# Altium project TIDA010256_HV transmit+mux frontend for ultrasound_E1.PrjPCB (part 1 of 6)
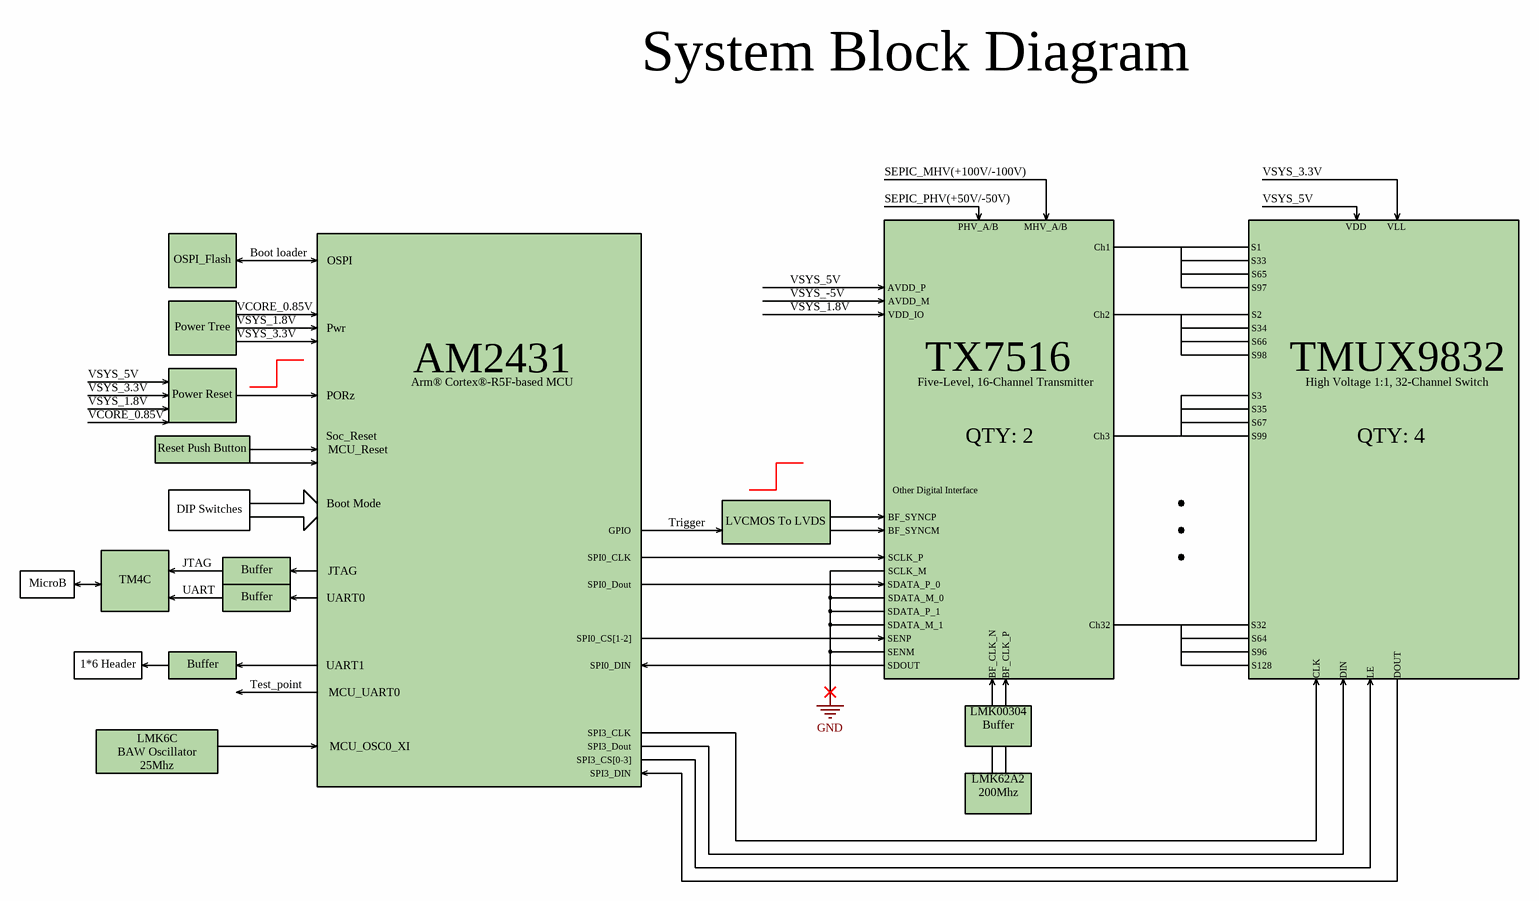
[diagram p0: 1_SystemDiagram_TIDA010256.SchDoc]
CopyrightYear: 2023; PCB_Layout: Jason Ding / Michael Rosa; PCB_Rev: E1; PRJ_Customer: Public Release; PRJ_Engineer: Sanjay Pithadia; PRJ_Number: TIDA-010256; PRJ_Title: HV transmit+mux frontend for ultrasound; SCH_Rev: E1; TechSupport: http://www.ti.com/support; TID: TIDA-010256
18 sheets, 806 parts. Net scope: global (net labels, ports and power ports of the same name join across sheets).
Board file: TIDA010256_HV transmit+mux frontend for ultrasound_E1.PcbDoc
Sheets:
  1_SystemDiagram_TIDA010256.SchDoc
  10_Power_Tree.SchDoc
  11_HighVoltage_PowerSupply.SchDoc
  12_LowVoltage_PowerSupplies01.SchDoc
  13_LowVoltage_PowerSupplies02.SchDoc
  14_XDS110_Debugger.SchDoc
  15_AM243x_BootMode.SchDoc
  16_AM243x_Reset.SchDoc
  17_AM243x_SocPower.SchDoc
  18_AM243x_Pinout.SchDoc
  19_Clock_Gen.SchDoc
  20_TX7516_PartAPinout.SchDoc
  21_TX7516_PartBPinout.SchDoc
  22_TMUX9832(0-64)_Pinout.SchDoc
  23_TMUX9832(65-128)_Pinout.SchDoc
  24_TX_Connector(no load resitor).SchDoc
  25_RX_Connector.SchDoc
  Hardware.SchDoc

## Sheet 1_SystemDiagram_TIDA010256.SchDoc
size 431 x 279 mm; Date: Not shown in title block; ApprovedBy: Not shown in title block; CheckedBy: Not shown in title block; Author: Not shown in title block; CompanyName: Not shown in title block; DrawnBy: Jason Ding; Engineer: Not shown in title block; Organization: Not shown in title block; Address1: Not shown in title block; Address2: Not shown in title block; Address3: Not shown in title block; Address4: Not shown in title block; DocumentNumber: 1; Revision: Use project parameter SCH_Rev; SheetNumber: 1; SheetTotal: 18; PageSetup: Record=PageOptions¦CenterHorizontal=True¦CenterVertical=True¦PrintScale=1.00¦XCorrection=1.00¦YCorrection=1.00¦PrintKind=0¦BorderSize=5000000¦LeftOffset=0¦BottomOffset=0¦Orientation=2¦PaperLength=1000¦PaperWidth=1000¦Scale=100¦PaperSource=15¦PrintQuality=600¦MediaType=1¦DitherType=10¦PaperKind=Letter¦PrintScaleMode=1

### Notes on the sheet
- System Block Diagram
- SEPIC_MHV(+100V/-100V)
- VSYS_3.3V
- OSPI_Flash
- Boot loader
- OSPI
- SEPIC_PHV(+50V/-50V)
- PHV_A/B
- MHV_A/B
- Ch1
- S1
- S33
- VSYS_5V
- VDD
- VLL
- VCORE_0.85V
- VSYS_1.8V
- Pwr
- VSYS_-5V
- VDD_IO
- AVDD_P
- AVDD_M
- Ch2
- S2
- S34
- S65
- S97
- Power Reset
- Power Tree
- PORz
- AM2431
- Arm® Cortex®-R5F-based MCU
- TX7516
- Five-Level, 16-Channel Transmitter
- S3
- S98
- S66
- TMUX9832
- High Voltage 1:1, 32-Channel Switch
- Reset Push Button
- Soc_Reset
- MCU_Reset
- QTY: 2
- Ch3
- S35
- S99
- S67
- QTY: 4
- DIP Switches
- Boot Mode
- GPIO
- Trigger
- LVCMOS To LVDS
- BF_SYNCP
- BF_SYNCM
- Other Digital Interface
- MicroB
- TM4C
- JTAG
- UART
- Buffer
- UART0
- SPI0_CLK
- SPI0_Dout
- SCLK_P
- SCLK_M
- SDATA_P_0
- SDATA_M_0
- 1*6 Header
- UART1
- SPI0_CS[1-2]
- SPI0_DIN
- SENP
- SENM
- SDOUT
- SDATA_P_1
- SDATA_M_1
- Ch32
- S32
- S64
- S96
- S128
- Test_point
- MCU_UART0
- SPI3_CLK
- LMK00304
- BF_CLK_N
- BF_CLK_P
- CLK
- DIN
- LE
- DOUT
- BAW Oscillator
- LMK6C
- 25Mhz
- MCU_OSC0_XI
- SPI3_CS[0-3]
- SPI3_Dout
- SPI3_DIN
- LMK62A2
- 200Mhz
- Labels drawn without touching a wire or pin: GND

## Sheet 10_Power_Tree.SchDoc
size 431 x 279 mm; Date: Not shown in title block; ApprovedBy: Not shown in title block; CheckedBy: Not shown in title block; Author: Not shown in title block; CompanyName: Not shown in title block; Engineer: Not shown in title block; Organization: Not shown in title block; Address1: Not shown in title block; Address2: Not shown in title block; Address3: Not shown in title block; Address4: Not shown in title block; DocumentNumber: 2; Revision: Use project parameter SCH_Rev; SheetNumber: 2; SheetTotal: 18; PageSetup: Record=PageOptions¦CenterHorizontal=True¦CenterVertical=True¦PrintScale=1.00¦XCorrection=1.00¦YCorrection=1.00¦PrintKind=0¦BorderSize=5000000¦LeftOffset=0¦BottomOffset=0¦Orientation=2¦PaperLength=1000¦PaperWidth=1000¦Scale=100¦PaperSource=15¦PrintQuality=600¦MediaType=1¦DitherType=10¦PaperKind=Letter¦PrintScaleMode=1
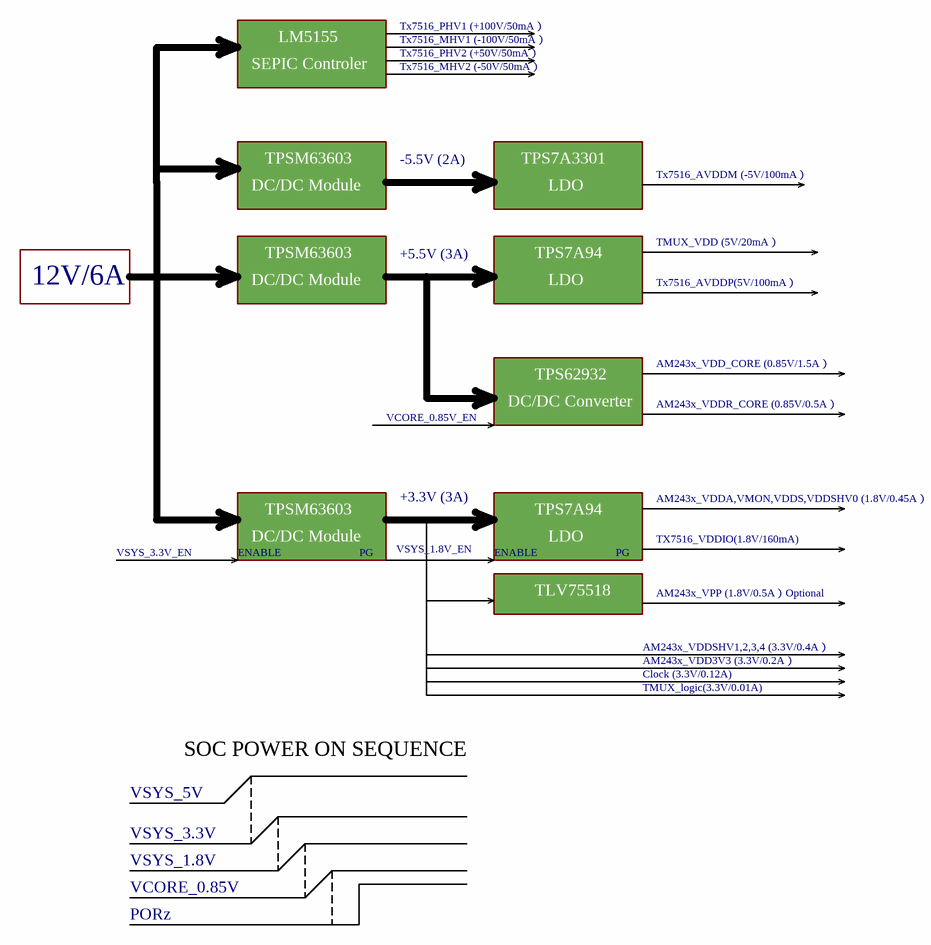
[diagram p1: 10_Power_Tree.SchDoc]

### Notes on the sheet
- LM5155
- Tx7516_PHV1 (+100V/50mA）
- Tx7516_MHV1 (-100V/50mA）
- Tx7516_PHV2 (+50V/50mA）
- SEPIC Controler
- Tx7516_MHV2 (-50V/50mA）
- DC/DC Module
- TPSM63603
- -5.5V (2A)
- TPS7A3301
- LDO
- Tx7516_AVDDM (-5V/100mA）
- +5.5V (3A)
- TPS7A94
- TMUX_VDD (5V/20mA）
- 12V/6A
- Tx7516_AVDDP(5V/100mA）
- TPS62932
- AM243x_VDD_CORE (0.85V/1.5A）
- VCORE_0.85V_EN
- DC/DC Converter
- AM243x_VDDR_CORE (0.85V/0.5A）
- +3.3V (3A)
- AM243x_VDDA,VMON,VDDS,VDDSHV0 (1.8V/0.45A）
- VSYS_3.3V_EN
- ENABLE
- PG
- VSYS_1.8V_EN
- TLV75518
- TX7516_VDDIO(1.8V/160mA)
- AM243x_VPP (1.8V/0.5A）Optional
- AM243x_VDDSHV1,2,3,4 (3.3V/0.4A）
- AM243x_VDD3V3 (3.3V/0.2A）
- Clock (3.3V/0.12A)
- TMUX_logic(3.3V/0.01A)
- VSYS_5V
- SOC POWER ON SEQUENCE
- VSYS_3.3V
- VSYS_1.8V
- VCORE_0.85V
- PORz

## Sheet 11_HighVoltage_PowerSupply.SchDoc
size A2; Date: Not shown in title block; ApprovedBy: Not shown in title block; CheckedBy: Not shown in title block; Author: Not shown in title block; CompanyName: Not shown in title block; Engineer: Not shown in title block; Organization: Not shown in title block; Address1: Not shown in title block; Address2: Not shown in title block; Address3: Not shown in title block; Address4: Not shown in title block; DocumentNumber: 3; Revision: Use project parameter SCH_Rev; SheetNumber: 3; SheetTotal: 18; PageSetup: Record=PageOptions¦CenterHorizontal=True¦CenterVertical=True¦PrintScale=0.69¦XCorrection=1.00¦YCorrection=1.00¦PrintKind=0¦BorderSize=5000000¦LeftOffset=0¦BottomOffset=0¦Orientation=2¦PaperLength=1000¦PaperWidth=1000¦Scale=100¦PaperSource=15¦PrintQuality=600¦MediaType=1¦DitherType=10¦PaperKind=Letter¦PrintScaleMode=1
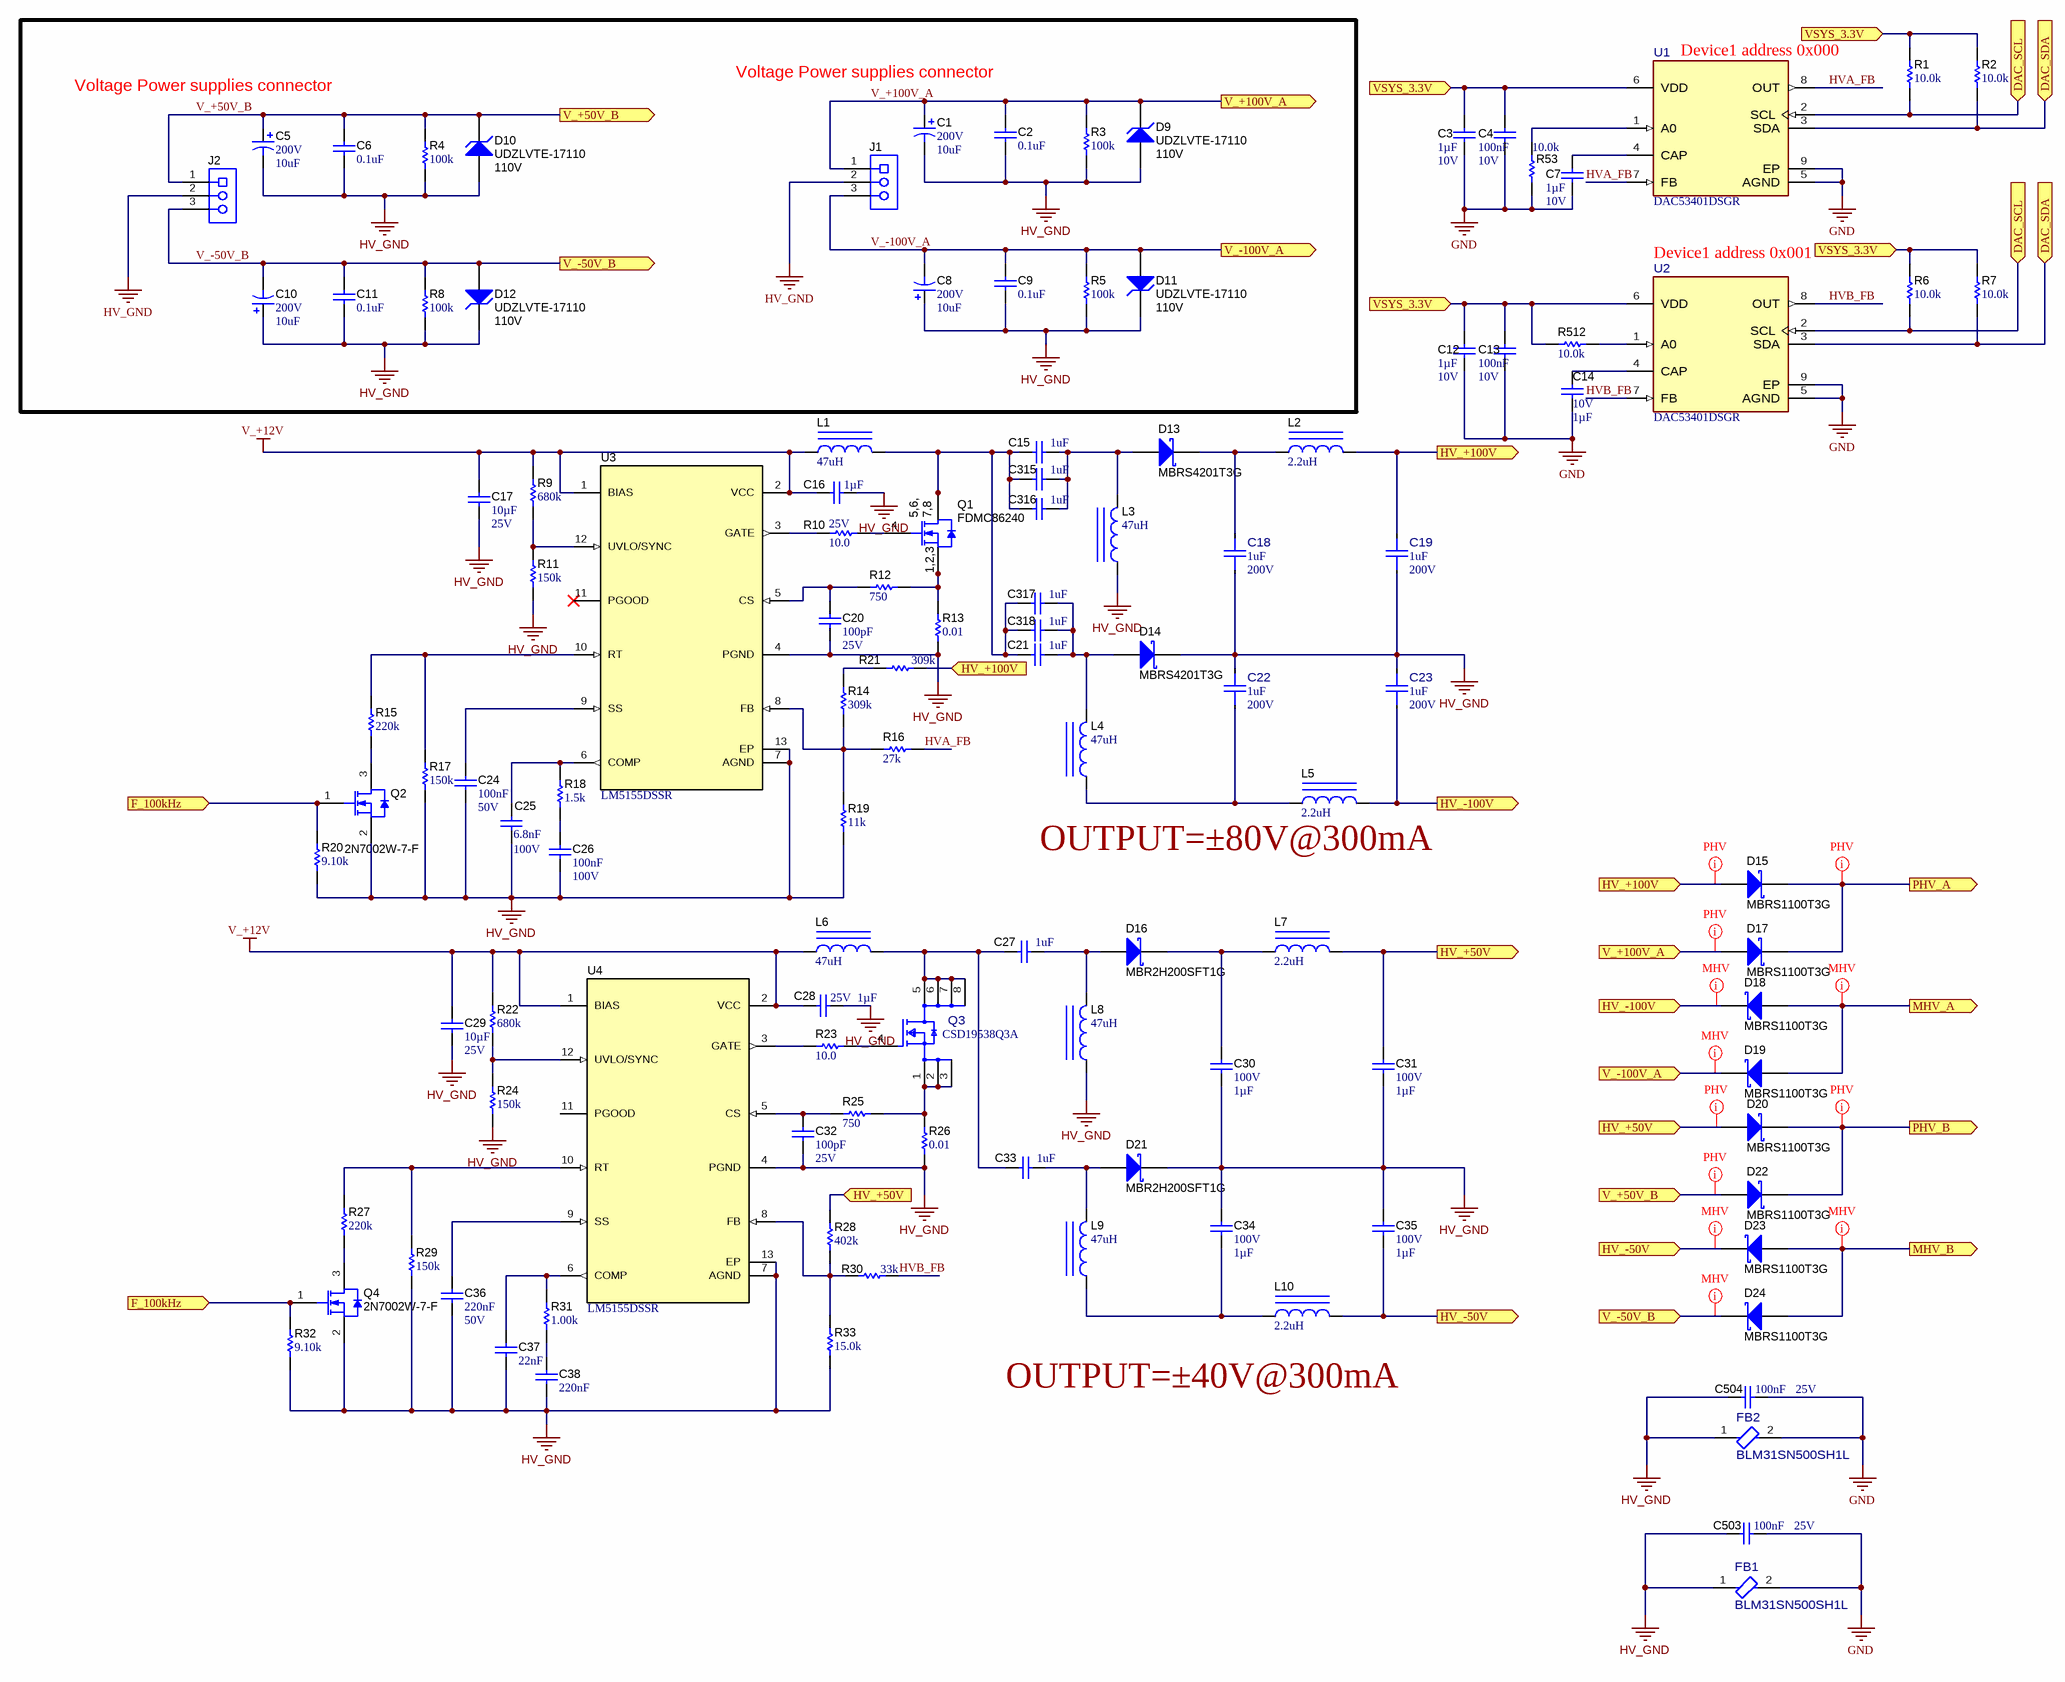
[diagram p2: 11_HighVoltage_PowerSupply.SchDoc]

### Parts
C1  VDC_V: 200V  ValueDisplayed: 10uF  [CAPPRD350W60D800H1150]  (hidden comment: 200LLE10MEFC8X11.5)
C2  ValueDisplayed: 0.1uF  [1206]  (hidden comment: C1206C104K2RACTU)
C3  Cap_F: 1µF  VDC_V: 10V  [0603]  (hidden comment: C0603X105J8RAC7867)
C4  Cap_F: 100nF  VDC_V: 10V  [0603]  (hidden comment: C0603C104K8RACTU)
C5  VDC_V: 200V  ValueDisplayed: 10uF  [CAPPRD350W60D800H1150]  (hidden comment: 200LLE10MEFC8X11.5)
C6  ValueDisplayed: 0.1uF  [1206]  (hidden comment: C1206C104K2RACTU)
C7  Cap_F: 1µF  VDC_V: 10V  [0603]  (hidden comment: C0603X105J8RAC7867)
C8  VDC_V: 200V  ValueDisplayed: 10uF  [CAPPRD350W60D800H1150]  (hidden comment: 200LLE10MEFC8X11.5)
C9  ValueDisplayed: 0.1uF  [1206]  (hidden comment: C1206C104K2RACTU)
C10  VDC_V: 200V  ValueDisplayed: 10uF  [CAPPRD350W60D800H1150]  (hidden comment: 200LLE10MEFC8X11.5)
C11  ValueDisplayed: 0.1uF  [1206]  (hidden comment: C1206C104K2RACTU)
C12  Cap_F: 1µF  VDC_V: 10V  [0603]  (hidden comment: C0603X105J8RAC7867)
C13  Cap_F: 100nF  VDC_V: 10V  [0603]  (hidden comment: C0603C104K8RACTU)
C14  Cap_F: 1µF  VDC_V: 10V  [0603]  (hidden comment: C0603X105J8RAC7867)
C15  ValueDisplayed: 1uF  [1206_180]  (hidden comment: GRM31CR72A105KA01L)
C16  Cap_F: 1µF  VDC_V: 25V  [0603]  (hidden comment: 06033C105KAT2A)
C17  Cap_F: 10µF  VDC_V: 25V  [0805_HV]  (hidden comment: GRM21BZ71E106KE15L)
C18  ValueDisplayed: 1uF  VDC_V: 200V  [FP-1812Y2500105KXTWS2_1812-MFG]  (hidden comment: 18122C105JAT2A)
C19  ValueDisplayed: 1uF  VDC_V: 200V  [FP-1812Y2500105KXTWS2_1812-MFG]  (hidden comment: 18122C105JAT2A)
C20  Cap_F: 100pF  VDC_V: 25V  [0603]  (hidden comment: 06033C101KAT2A)
C21  ValueDisplayed: 1uF  [1206_180]  (hidden comment: GRM31CR72A105KA01L)
C22  ValueDisplayed: 1uF  VDC_V: 200V  [FP-1812Y2500105KXTWS2_1812-MFG]  (hidden comment: 18122C105JAT2A)
C23  ValueDisplayed: 1uF  VDC_V: 200V  [FP-1812Y2500105KXTWS2_1812-MFG]  (hidden comment: 18122C105JAT2A)
C24  Cap_F: 100nF  VDC_V: 50V  [0603]  (hidden comment: GRM188R71H224KAC4D)
C25  Cap_F: 6.8nF  VDC_V: 100V  [0603]  (hidden comment: GRM188R72A682KA01D)
C26  Cap_F: 100nF  VDC_V: 100V  [0603]  (hidden comment: GRM188R72A104KA35D)
C27  ValueDisplayed: 1uF  [1206_180]  (hidden comment: GRM31CR72A105KA01L)
C28  Cap_F: 1µF  VDC_V: 25V  [0603]  (hidden comment: 06033C105KAT2A)
C29  Cap_F: 10µF  VDC_V: 25V  [0805_HV]  (hidden comment: GRM21BZ71E106KE15L)
C30  VDC_V: 100V  ValueDisplayed: 1µF  [0805_HV]  (hidden comment: C2012X7S2A105K125AE)
C31  VDC_V: 100V  ValueDisplayed: 1µF  [0805_HV]  (hidden comment: C2012X7S2A105K125AE)
C32  Cap_F: 100pF  VDC_V: 25V  [0603]  (hidden comment: 06033C101KAT2A)
C33  ValueDisplayed: 1uF  [1206_180]  (hidden comment: GRM31CR72A105KA01L)
C34  VDC_V: 100V  ValueDisplayed: 1µF  [0805_HV]  (hidden comment: C2012X7S2A105K125AE)
C35  VDC_V: 100V  ValueDisplayed: 1µF  [0805_HV]  (hidden comment: C2012X7S2A105K125AE)
C36  Cap_F: 220nF  VDC_V: 50V  [0603]  (hidden comment: GRM188R71H224KAC4D)
C37  Cap_F: 22nF  [0603]  (hidden comment: 885012206034)
C38  Cap_F: 220nF  [0603]  (hidden comment: 885012206048)
C315  ValueDisplayed: 1uF  [1206_180]  (hidden comment: GRM31CR72A105KA01L)
C316  ValueDisplayed: 1uF  [1206_180]  (hidden comment: GRM31CR72A105KA01L)
C317  ValueDisplayed: 1uF  [1206_180]  (hidden comment: GRM31CR72A105KA01L)
C318  ValueDisplayed: 1uF  [1206_180]  (hidden comment: GRM31CR72A105KA01L)
C503  Cap_F: 100nF  VDC_V: 25V  [0603]  (hidden comment: C0603C104J3RAC)
C504  Cap_F: 100nF  VDC_V: 25V  [0603]  (hidden comment: C0603C104J3RAC)
D9  UDZLVTE-17110  value 110V  [SOD-323F]
D10  UDZLVTE-17110  value 110V  [SOD-323F]
D11  UDZLVTE-17110  value 110V  [SOD-323F]
D12  UDZLVTE-17110  value 110V  [SOD-323F]
D13  MBRS4201T3G  [SMC]
D14  MBRS4201T3G  [SMC]
D15  MBRS1100T3G  [SMB]
D16  MBR2H200SFT1G  [SOD-123FL]
D17  MBRS1100T3G  [SMB]
D18  MBRS1100T3G  [SMB]
D19  MBRS1100T3G  [SMB]
D20  MBRS1100T3G  [SMB]
D21  MBR2H200SFT1G  [SOD-123FL]
D22  MBRS1100T3G  [SMB]
D23  MBRS1100T3G  [SMB]
D24  MBRS1100T3G  [SMB]
FB1  BLM31SN500SH1L  [FP-BLM31SN500SH1L_1206-MFG]
FB2  BLM31SN500SH1L  [FP-BLM31SN500SH1L_1206-MFG]
J1  1725669  [Phoenix_1725669]  (value not drawn)
J2  1725669  [Phoenix_1725669]  (value not drawn)
L1  ValueDisplayed: 47uH  [WE-PD_1210]  (hidden comment: 7447709470)
L2  ValueDisplayed: 2.2uH  [0603]  (hidden comment: LQM18PN2R2MFR)
L3  ValueDisplayed: 47uH  [WE-PD2-XL]  (hidden comment: 744776147)
L4  ValueDisplayed: 47uH  [WE-PD2-XL]  (hidden comment: 744776147)
L5  ValueDisplayed: 2.2uH  [0603]  (hidden comment: LQM18PN2R2MFR)
L6  ValueDisplayed: 47uH  [WE-PD_1210]  (hidden comment: 7447709470)
L7  ValueDisplayed: 2.2uH  [0603]  (hidden comment: LQM18PN2R2MFR)
L8  ValueDisplayed: 47uH  [WE-PD2-XL]  (hidden comment: 744776147)
L9  ValueDisplayed: 47uH  [WE-PD2-XL]  (hidden comment: 744776147)
L10  ValueDisplayed: 2.2uH  [0603]  (hidden comment: LQM18PN2R2MFR)
Q1  FDMC86240  [TRANS_Fairchild_MLP08S]
Q2  2N7002W-7-F  [SOT-323]
Q3  CSD19538Q3A  [DNH0008A-MFG]
Q4  2N7002W-7-F  [SOT-323]
R1  ValueDisplayed: 10.0k  [0603]  (hidden comment: RNCF0603TKY10K0)
R2  ValueDisplayed: 10.0k  [0603]  (hidden comment: RNCF0603TKY10K0)
R3  ValueDisplayed: 100k  [1206]  (hidden comment: TNPW1206100KBEEA)
R4  ValueDisplayed: 100k  [1206]  (hidden comment: TNPW1206100KBEEA)
R5  ValueDisplayed: 100k  [1206]  (hidden comment: TNPW1206100KBEEA)
R6  ValueDisplayed: 10.0k  [0603]  (hidden comment: RNCF0603TKY10K0)
R7  ValueDisplayed: 10.0k  [0603]  (hidden comment: RNCF0603TKY10K0)
R8  ValueDisplayed: 100k  [1206]  (hidden comment: TNPW1206100KBEEA)
R9  ValueDisplayed: 680k  [0805_HV]  (hidden comment: CRCW0805215KFKEA)
R10  ValueDisplayed: 10.0  [0603]  (hidden comment: CRCW060310R0FKEA)
R11  ValueDisplayed: 150k  [0805_HV]  (hidden comment: CRCW0805215KFKEA)
R12  ValueDisplayed: 750  [0603]  (hidden comment: CRCW0603750RFKEA)
R13  ValueDisplayed: 0.01  [0612]  (hidden comment: ERJ-B2CFR01V)
R14  ValueDisplayed: 309k  [0603]  (hidden comment: CRCW0603309KFKEA)
R15  ValueDisplayed: 220k  [0603]  (hidden comment: RG1608P-224-B-T5)
R16  ValueDisplayed: 27k  [0603]  (hidden comment: CRCW060327K0JNEA)
R17  ValueDisplayed: 150k  [0603]  (hidden comment: RT0603BRD07150KL)
R18  ValueDisplayed: 1.5k  [0603]  (hidden comment: CRCW06031K50JNEA)
R19  ValueDisplayed: 11k  [0603]  (hidden comment: CRCW060311K0JNEA)
R20  ValueDisplayed: 9.10k  [0603]  (hidden comment: RG1608P-912-B-T5)
R21  ValueDisplayed: 309k  [0603]  (hidden comment: CRCW0603309KFKEA)
R22  ValueDisplayed: 680k  [0805_HV]  (hidden comment: CRCW0805215KFKEA)
R23  ValueDisplayed: 10.0  [0603]  (hidden comment: CRCW060310R0FKEA)
R24  ValueDisplayed: 150k  [0805_HV]  (hidden comment: CRCW0805215KFKEA)
R25  ValueDisplayed: 750  [0603]  (hidden comment: CRCW0603750RFKEA)
R26  ValueDisplayed: 0.01  [0612]  (hidden comment: ERJ-B2CFR01V)
R27  ValueDisplayed: 220k  [0603]  (hidden comment: RG1608P-224-B-T5)
R28  ValueDisplayed: 402k  [0603]  (hidden comment: CRCW0603402KFKEA)
R29  ValueDisplayed: 150k  [0603]  (hidden comment: RT0603BRD07150KL)
R30  ValueDisplayed: 33k  [0603]  (hidden comment: CRCW060333K0JNEA)
R31  ValueDisplayed: 1.00k  [0603]  (hidden comment: RC0603FR-071KL)
R32  ValueDisplayed: 9.10k  [0603]  (hidden comment: RG1608P-912-B-T5)
R33  ValueDisplayed: 15.0k  [0603]  (hidden comment: CRCW060315K0FKEA)
R53  ValueDisplayed: 10.0k  [0603]  (hidden comment: RNCF0603TKY10K0)
R512  ValueDisplayed: 10.0k  [0603]  (hidden comment: RNCF0603TKY10K0)
U1  DAC53401DSGR  [DSG0008A-MFG]
U2  DAC53401DSGR  [DSG0008A-MFG]
U3  LM5155DSSR  [DSS0012B]
U4  LM5155DSSR  [DSS0012B]

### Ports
DAC_SCL (in), DAC_SDA (in), F_100kHz (in), HV_+50V (in), HV_+50V (out), HV_+100V (in), HV_+100V (out), HV_-50V (in), HV_-50V (out), HV_-100V (in), HV_-100V (out), MHV_A (out), MHV_B (out), PHV_A (out), PHV_B (out), V_+50V_B (in), V_+50V_B (out), V_+100V_A (in), V_+100V_A (out), V_-50V_B (in), V_-50V_B (out), V_-100V_A (in), V_-100V_A (out), VSYS_3.3V (in)

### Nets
GND: C3.2 C4.2 C7.2 C12.2 C13.2 C14.2 C503.1 C504.1 FB1.2 FB2.2 R53.1 U1.5(AGND) U1.9(EP) U2.5(AGND) U2.9(EP)
HV_GND: C1.2(-) C2.2 C5.2(-) C6.2 C8.1(+) C9.2 C10.1(+) C11.2 C16.2 C17.2 C18.1 C19.1 C20.2 C22.2 C23.2 C24.2 C25.2 C26.2 C28.2 C29.2 C30.2 C31.2 C32.2 C34.1 C35.1 C36.2 C37.2 C38.2 C503.2 C504.2 D9.2(A) D10.2(A) D11.1(K) D12.1(K) D14.1(K) D21.1(K) FB1.1 FB2.1 J1.2 J2.2 L3.1 L8.1 Q2.2(S) Q4.2(S) R3.1 R4.1 R5.1 R8.1 R11.1 R13.1 R17.1 R19.1 R20.1 R24.1 R26.1 R29.1 R32.1 R33.1 U3.4(PGND) U3.7(AGND) U3.13(EP) U4.4(PGND) U4.7(AGND) U4.13(EP)
MHV_A: D18.2(A) D19.2(A) ; port MHV_A
MHV_B: D23.2(A) D24.2(A) ; port MHV_B
PHV_A: D15.1(K) D17.1(K) ; port PHV_A
PHV_B: D20.1(K) D22.1(K) ; port PHV_B
V_+12V: C16.1 C17.1 C28.1 C29.1 L1.1 L6.1 R9.2 R22.2 U3.1(BIAS) U3.2(VCC) U4.1(BIAS) U4.2(VCC)
HVA_FB: R16.2 U1.7(FB) U1.8(OUT)
HVB_FB: R30.2 U2.7(FB) U2.8(OUT)
V_+50V_B: C5.1(+) C6.1 D10.1(K) D22.2(A) J2.1 R4.2 ; port V_+50V_B
V_+100V_A: C1.1(+) C2.1 D9.1(K) D17.2(A) J1.1 R3.2 ; port V_+100V_A
V_-50V_B: C10.2(-) C11.1 D12.2(A) D24.1(K) J2.3 R8.2 ; port V_-50V_B
V_-100V_A: C8.2(-) C9.1 D11.2(A) D19.1(K) J1.3 R5.2 ; port V_-100V_A
VSYS_3.3V: C3.1 C4.1 C12.1 C13.1 R1.2 R2.2 R6.2 R7.2 R512.2 U1.6(VDD) U2.6(VDD) ; port VSYS_3.3V
NetC7_1: C7.1 U1.4(CAP)
NetC14_1: C14.1 U2.4(CAP)
NetC15_1: C15.1 C315.1 C316.1 D13.2(A) L3.2
NetC15_2: C15.2 C21.2 C315.2 C316.2 C317.2 C318.2 L1.2 Q1.5(D) Q1.6(D) Q1.7(D) Q1.8(D) Q1.9(D)
NetC18_2: C18.2 D13.1(K) L2.1
NetC19_2: C19.2 D15.2(A) L2.2 R21.1 ; port HV_+100V
NetC20_1: C20.1 R12.1 U3.5(CS)
NetC21_1: C21.1 C317.1 C318.1 D14.2(A) L4.2
NetC22_1: C22.1 L4.1 L5.1
NetC23_1: C23.1 D18.1(K) L5.2 ; port HV_-100V
NetC24_1: C24.1 U3.9(SS)
NetC25_1: C25.1 R18.2 U3.6(COMP)
NetC26_1: C26.1 R18.1
NetC27_1: C27.1 D16.2(A) L8.2
NetC27_2: C27.2 C33.2 L6.2 Q3.5(D) Q3.6(D) Q3.7(D) Q3.8(D)
NetC30_1: C30.1 D16.1(K) L7.1
NetC31_1: C31.1 D20.2(A) L7.2 R28.2 ; port HV_+50V
NetC32_1: C32.1 R25.1 U4.5(CS)
NetC33_1: C33.1 D21.2(A) L9.2
NetC34_2: C34.2 L9.1 L10.1
NetC35_2: C35.2 D23.1(K) L10.2 ; port HV_-50V
NetC36_1: C36.1 U4.9(SS)
NetC37_1: C37.1 R31.2 U4.6(COMP)
NetC38_1: C38.1 R31.1
NetQ1_1: Q1.1(S) Q1.2(S) Q1.3(S) R12.2 R13.2
NetQ1_4: Q1.4(G) R10.2
NetQ2_1: Q2.1(G) Q4.1(G) R20.2 R32.2 ; port F_100kHz
NetQ2_3: Q2.3(D) R15.1
NetQ3_1: Q3.1(S) Q3.2(S) Q3.3(S) R25.2 R26.2
NetQ3_4: Q3.4(G) R23.2
NetQ4_3: Q4.3(D) R27.1
NetR1_1: R1.1 R6.1 U1.2(SCL) U2.2(SCL) ; port DAC_SCL
NetR2_1: R2.1 R7.1 U1.3(SDA) U2.3(SDA) ; port DAC_SDA
NetR9_1: R9.1 R11.2 U3.12(UVLO/SYNC)
NetR10_1: R10.1 U3.3(GATE)
NetR14_1: R14.1 R16.1 R19.2 U3.8(FB)
NetR14_2: R14.2 R21.2
NetR15_2: R15.2 R17.2 U3.10(RT)
NetR22_1: R22.1 R24.2 U4.12(UVLO/SYNC)
NetR23_1: R23.1 U4.3(GATE)
NetR27_2: R27.2 R29.2 U4.10(RT)
NetR28_1: R28.1 R30.1 R33.2 U4.8(FB)
NetR53_2: R53.2 U1.1(A0)
NetR512_1: R512.1 U2.1(A0)

Not connected (* = marked no-connect by the designer): U3 11(PGOOD)*; U4 11(PGOOD)

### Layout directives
net class PHV: NetC19_2, NetC31_1, PHV_A, PHV_B, V_+50V_B, V_+100V_A
net class MHV: MHV_A, MHV_B, NetC23_1, NetC35_2, V_-50V_B, V_-100V_A

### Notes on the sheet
- Voltage Power supplies connector
- (near U1) Device1 address 0x000
- Device1 address 0x001
- (near L5) OUTPUT=±80V@300mA
- (near L10) OUTPUT=±40V@300mA

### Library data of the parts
C1 C5 C8 C10 = CMP-0009946-2: CAP, AL, 10 uF, 200 V, +/- 20%, TH; Manufacturer: Rubycon; TaMin_C: -40°C; Polarized: Y; SizeAreaWB_mm2: 100; Value1: Unknown; U/M: EA; Value: 10uF; TaMax_C: 105°C; SizeZ_mm: 13; SizeX_mm: 8; Cap_Case: Radial 8x11.5mm; SizeArea_mm2: 64; CompType: Capacitor; AEC Qualified: N; Cap_F: 10µF; IRMS_A: 80mA; AEC Category: Q200
C2 C6 C9 C11 = CMP-0008585-2: CAP, CERM, 0.1 uF, 200 V, +/- 10%, X7R, 1206; Manufacturer: Kemet; Polarized: N; Value: 0.1uF; U/M: EA; Cap_F: 100nF; Value1: Unknown; VDC_V: 200V; TaMin_C: -55°C; TaMax_C: 125°C; SizeArea_mm2: 5.12; SizeAreaWB_mm2: 10.92; SizeX_mm: 3.2; SizeY_mm: 1.6; SizeZ_mm: 1.35; AEC Category: Q200
C3 C7 C12 C14 = CMP-0084112-1: CAP, CERM, 1 µF, 10 V,+/- 5%, X7R, AEC-Q200 Grade 1, 0603; Manufacturer: Kemet; SizeAreaWB_mm2: 4.68; SizeArea_mm2: 1.28; AEC Qualified: Y; AEC Category: Q200; Value: 1uF; TaMax_C: 125°C; SizeZ_mm: 1; Polarized: N; TaMin_C: -55°C; SizeY_mm: 0.8; U/M: EA; SizeX_mm: 1.6
C4 C13 = CMP-0006862-5: CAP, CERM, 0.1 uF, 10 V, +/- 10%, X7R, 0603; Manufacturer: Kemet; TaMin_C: -55°C; Polarized: N; SizeAreaWB_mm2: 4.68; Value1: Unknown; U/M: EA; Value: 0.1uF; TaMax_C: 125°C; SizeZ_mm: 1; SizeX_mm: 1.6; SizeY_mm: 0.8; SizeArea_mm2: 1.28; AEC Category: Q200
C15 C21 C27 C33 C315-C318 = CMP-0008970-2: CAP, CERM, 1 uF, 100 V, +/- 10%, X7R, 1206; Manufacturer: MuRata; TaMin_C: -55°C; Polarized: N; SizeAreaWB_mm2: 10.92; Value1: Unknown; U/M: EA; Value: 1uF; TaMax_C: 125°C; SizeZ_mm: 1.8; SizeX_mm: 3.2; SizeY_mm: 1.6; Cap_Case: 2220; Value2: 100V; SizeArea_mm2: 5.12; Cap_F: 1µF; AEC Category: Q200
C16 C28 = CMP-0006754-4: CAP, CERM, 1 uF, 25 V, +/- 10%, X7R, 0603; Manufacturer: AVX; TaMin_C: -55°C; Polarized: N; SizeAreaWB_mm2: 4.68; Value1: Unknown; U/M: EA; Value: 1uF; TaMax_C: 125°C; SizeZ_mm: 1; SizeX_mm: 1.6; SizeY_mm: 0.8; SizeArea_mm2: 1.28; AEC Category: Q200
C17 C29 = CMP-0008378-2: CAP, CERM, 10 uF, 25 V, +/- 10%, X7R, 0805; Manufacturer: MuRata; TaMin_C: -55°C; Polarized: N; SizeAreaWB_mm2: 6.75; Value1: Unknown; U/M: EA; Value: 10uF; TaMax_C: 125°C; SizeZ_mm: 1.45; SizeX_mm: 2; SizeY_mm: 1.25; Cap_Case: 0805; SizeArea_mm2: 2.5; AEC Category: Q200
C18 C19 C22 C23 = CMP-0094501-1: 1 µF ±10% 200V Ceramic Capacitor X7R 1812 (4532 Metric); PartNumber: 1812Y2500105KXTWS2; Manufacturer: Knowles Syfer; AEC Qualified: No; SizeZ_mm: 3.5mm; Cap_F: 1µF; Value: 1µF; TempCo: 15%
C20 C32 = CMP-0006751-4: CAP, CERM, 100 pF, 25 V, +/- 10%, X7R, 0603; Manufacturer: AVX; TaMin_C: -55°C; Polarized: N; SizeAreaWB_mm2: 4.68; Value1: Unknown; U/M: EA; Value: 100pF; TaMax_C: 125°C; SizeZ_mm: 1; SizeX_mm: 1.6; SizeY_mm: 0.8; SizeArea_mm2: 1.28; AEC Category: Q200
C24 = CMP-0007445-4: CAP, CERM, 100 nF, 50 V, +/- 10%, X7R, 0603; Manufacturer: MuRata; TaMin_C: -55°C; Polarized: N; SizeAreaWB_mm2: 4.68; Value1: Unknown; U/M: EA; Value: 0.22uF; TaMax_C: 125°C; SizeZ_mm: 1; SizeX_mm: 1.6; SizeY_mm: 0.8; SizeArea_mm2: 1.28; AEC Category: Q200
C25 = CMP-0007487-4: CAP, CERM, 6800 pF, 100 V, +/- 10%, X7R, 0603; Manufacturer: MuRata; TaMin_C: -55°C; Polarized: N; SizeAreaWB_mm2: 4.68; Value1: Unknown; U/M: EA; Value: 6800pF; TaMax_C: 125°C; SizeZ_mm: 1; SizeX_mm: 1.6; SizeY_mm: 0.8; SizeArea_mm2: 1.28; AEC Category: Q200
C26 = CMP-0007469-4: CAP, CERM, 0.1 uF, 100 V, +/- 10%, X7R, 0603; Manufacturer: MuRata; TaMin_C: -55°C; Polarized: N; SizeAreaWB_mm2: 4.68; Value1: Unknown; U/M: EA; Value: 0.1uF; TaMax_C: 125°C; SizeZ_mm: 1; SizeX_mm: 1.6; SizeY_mm: 0.8; SizeArea_mm2: 1.28; AEC Category: Q200
C30 C31 C34 C35 = CMP-0750059-1: CAP, CERM, 1 µF, 100 V,+/- 10%, X7S, 0805; Manufacturer: TDK; TaMax_C: 125°C; SizeAreaWB_mm2: 6.75; SizeY_mm: 1.25; Green_REACh: Incomplete; TaMin_C: -55°C; Cap_Case: 0805; SizeZ_mm: 1.45; U/M: EA; SizeX_mm: 2; Polarized: N; Green_Lifecycle: Active; SizeArea_mm2: 2.5; Value: 1uF; AEC Category: Q200
C36 = CMP-0007445-4: CAP, CERM, 0.22 uF, 50 V, +/- 10%, X7R, 0603; Manufacturer: MuRata; TaMin_C: -55°C; Polarized: N; SizeAreaWB_mm2: 4.68; Value1: Unknown; U/M: EA; Value: 0.22uF; TaMax_C: 125°C; SizeZ_mm: 1; SizeX_mm: 1.6; SizeY_mm: 0.8; SizeArea_mm2: 1.28; AEC Category: Q200
C37 = CMP-0006826-4: CAP, CERM, 22nF, 16 V, +/- 10%, X7R, 0603; Manufacturer: Wurth Elektronik; TaMin_C: -55°C; Polarized: N; SizeAreaWB_mm2: 4.68; Value1: Unknown; U/M: EA; Value: 1000pF; TaMax_C: 125°C; SizeZ_mm: 1; SizeX_mm: 1.6; SizeY_mm: 0.8; Value2: 16V; SizeArea_mm2: 1.28; AEC Category: Q200
C38 = CMP-0006830-4: CAP, CERM, 0.22 uF, 16 V, +/- 10%, X7R, 0603; Manufacturer: Wurth Elektronik; TaMin_C: -55°C; Polarized: N; SizeAreaWB_mm2: 4.68; Value1: Unknown; U/M: EA; Value: 0.22uF; TaMax_C: 125°C; SizeZ_mm: 1; SizeX_mm: 1.6; SizeY_mm: 0.8; Value2: 16V; SizeArea_mm2: 1.28; AEC Category: Q200
C503 C504 = CMP-0006855-4: CAP, CERM, 0.1 uF, 25 V, +/- 5%, X7R, 0603; Manufacturer: Kemet; TaMin_C: -55°C; Polarized: N; SizeAreaWB_mm2: 4.68; Value1: Unknown; U/M: EA; Value: 0.1uF; TaMax_C: 125°C; SizeZ_mm: 1; SizeX_mm: 1.6; SizeY_mm: 0.8; SizeArea_mm2: 1.28; AEC Category: Q200
D9-D12 = CMP-0082118-3: Diode, Zener, 110 V, 200 mW, SOD-323F; Manufacturer: Rohm; SizeAreaWB_mm2: 7.875; SizeArea_mm2: 3.125; AEC Qualified: N; AEC Category: Q101; SizeZ_mm: 0.8; Power_W: 200mW; SizeY_mm: 1.25; Value1: 0.2W; SizeX_mm: 2.5
D13 D14 = CMP-0076995-2: Diode, Schottky, 200 V, 4 A, SMC; Manufacturer: ON Semiconductor; AEC Category: Q101; Vf_V: 860mV; Value: 200V; Green_REACh: Incomplete; SizeX_mm: 8.13; SizeY_mm: 6.22; Green_Lifecycle: Not Set; SizeZ_mm: 2.6; Value1: 4A; SizeArea_mm2: 50.5686; SizeAreaWB_mm2: 83.2686; TJmax_C: 150°C; Value2: 0.86V
D15 D17-D20 D22-D24 = CMP-0028521-2: Diode, Schottky, 100 V, 1 A, SMB; Manufacturer: ON Semiconductor; TJmax_C: 150°C; SizeY_mm: 3.81; RJC_CperW: 22; Value1: 1A; SizeAreaWB_mm2: 44.156; Green_Lifecycle: Active; Vr_V: 100V; SizeArea_mm2: 21.336; Vf_V: 750mV; SizeZ_mm: 2.6; Value: 100V; SizeX_mm: 5.6; Green_REACh: Passed; Value2: 0.75V; AEC Category: Q101
D16 D21 = CMP-0028776-2: Diode, Schottky, 200 V, 2 A, SOD-123FL; Manufacturer: ON Semiconductor; Value: 200V; TJmax_C: 150°C; SizeZ_mm: 0.98; Value1: 2A; Green_REACh: Incomplete; Vf_V: 940mV; Green_Lifecycle: Not Set; SizeAreaWB_mm2: 12.19; SizeY_mm: 1.65; AEC Qualified: N; SizeArea_mm2: 5.94; SizeX_mm: 3.6; AEC Category: Q101; Value2: 0.94V
FB1 FB2 = CMP-0093223-1: Chip Ferrite Bead Array, 1206, 50Ω @ 100MHz, 0.0016Ω, 25%, 12A; Manufacturer: Murata; AEC Grade: Grade 1; DCR_ohm: 1.6m; AEC Qualified: Yes; SizeZ_mm: 1.3mm; Import Ts: 1521846834; Ciiva Ids: 2806620
J1 J2 = CMP-0055500-1: Terminal Block, 3x1, 2.54 mm, TH; Manufacturer: Phoenix Contact; CNHeader: FALSE; Green_Lifecycle: Not Set; Green_REACh: Incomplete; CT: TRUE
L1 L6 = CMP-0064542-2: Inductor, Shielded Drum Core, Ferrite, 47 uH, 3.8 A, 0.04593 ohm, SMD; Manufacturer: Wurth Elektronik; Isat: 4.5A @ 10% inductance drop; Irms: 3.8A @ 40C rise; Green_Lifecycle: Active; SizeAreaWB_mm2: 196; Green_REACh: Passed; Value: 47uH; Imax_A: 3.8A; SizeZ_mm: 10; SizeX_mm: 12; SizeArea_mm2: 144; AEC Category: Q200; Ind_H: 47µH
L2 L5 L7 L10 = CMP-0058735-1: Inductor, Multilayer, Ferrite, 2.2 uH, 0.75 A, 0.03 ohm, SMD; Manufacturer: MuRata; Green_Lifecycle: Active; SizeAreaWB_mm2: 4.68; DCR_ohm: 0.03; Green_REACh: Passed; Value: 2.2uH; Imax_A: 7.5dA; SizeZ_mm: 1; SizeX_mm: 1.6; SizeY_mm: 0.8; Value2: 0.75A; SizeArea_mm2: 1.28; Ind_H: 2.2µH; AEC Category: Q200
L3 L4 L8 L9 = CMP-0064617-2: Inductor, Drum Core, Ferrite, 47 uH, 1.45 A, 0.095 ohm, SMD; Manufacturer: Wurth Elektronik; Isat: 1.62A @ 10% inductance drop; Irms: 1.45A @ 40C rise; Green_Lifecycle: Active; SizeAreaWB_mm2: 132; DCR_ohm: 0.095; Green_REACh: Passed; Value: 47uH; Imax_A: 1.45A; SizeZ_mm: 5.4; SizeX_mm: 10; SizeY_mm: 9; SizeArea_mm2: 90; Ind_H: 47µH; AEC Category: Q200
Q1 = CMP-0001055-1: MOSFET, N-CH, 150 V, Ta-16 A, QFN-8; Alternate Manufacturer: None; Manufacturer: Fairchild Semiconductor; SizeZ_mm: 0.8; ChType: N; Value2: 11 nC; VdsMax_V: 150V; SizeX_mm: 3.3; SizeAreaWB_mm2: 18.49; Vgs_V: 20V; QgTyp_nC: 11; Value: 150V; SizeArea_mm2: 10.89; AEC Category: Q101; IdsMax_A: 16A; U/M: EA
Q2 Q4 = CMP-0000776-1: MOSFET, N-CH, 60 V, 0.115 A, SOT-323; Alternate Manufacturer: None; Manufacturer: Diodes Inc.; SizeZ_mm: 1.1; ChType: N; Value1: 7; VdsMax_V: 60V; SizeX_mm: 2.2; Vgs_V: 20V; Value: 60V; Rdson45_ohm: 7.5; SizeArea_mm2: 4.84; AEC Category: Q101; IdsMax_A: 1.15dA; SizeAreaWB_mm2: 10.24; U/M: EA
Q3 = CMP-0047093-1: 100-V, N channel NexFET power MOSFET, single SON 3 mm x 3 mm, 61 mOhm; Manufacturer: Texas Instruments; AEC Qualified: No; IdsMax_A: 4.9A; QgTyp_nC: 4.3nC @ 10V; Rdson45_ohm: 49m; SizeZ_mm: 0.9mm; VdsMax_V: 1V; Vgs_V: 20V; ChMode: False; Drain To Source Breakdown Voltage: 100V; Input Capacitace At Vds: 349pF @ 50V; Number Of Channels: 1; Power_W: 2.8W; Pulse Drain Current: 37A; Reverse Recovery Charge: 94nC; Reverse Recovery Time: 32ns; Rthja Max: 55°C/W; Threshold Vgs Max: 3.8V; Threshold Vgs Min: 2.8V; TJmax_C: +150°C; Transconductance: 6.1S; Turn Off Delay Time: 7ns; Turn On Delay Time: 5ns; Typ Forward Diode Voltage: 0.85V
R1 R2 R6 R7 R53 R512 = CMP-0023626-3: RES, 10.0 k, 0.01%, 0.063 W, 0603; Manufacturer: Stackpole Electronics Inc; Power_W: 63mW; TempCo: 5 ppm/C; Value_Code: 10k0; U/M: EA; Value: 10.0k; Res_ohm: 10k; SizeX_mm: 1.6; SizeY_mm: 0.8; SizeZ_mm: 1; Value2: 0.063W; SizeArea_mm2: 1.28; VDC_V: 50V; AEC Category: Q200
R3-R5 R8 = CMP-0018819-2: RES, 100 k, 0.1%, 0.25 W, AEC-Q200 Grade 1, 1206; Manufacturer: Vishay-Dale; Value: 100k; Power_W: 250mW; Value2: 0.25W; VDC_V: 200V; TempCo: 25 ppm/C; SizeArea_mm2: 5.12; SizeX_mm: 3.2; SizeY_mm: 1.6; SizeZ_mm: 1.35; EIA_Code: E192; U/M: EA; AEC Category: Q200; AEC Qualified: Y; AEC Grade: 1
R9 R22 = CMP-0021048-3: RES, 680 k, 1%, 0.125 W, AEC-Q200 Grade 0, 0805; Manufacturer: Vishay-Dale; Power_W: 125mW; TempCo: 100 ppm/C; Value_Code: 215k; Value: 215k; EIA_Code: E96; SizeX_mm: 2; SizeY_mm: 1.25; SizeZ_mm: 1.45; Value2: 0.125W; SizeArea_mm2: 2.5; AEC Qualified: Y; VDC_V: 150V; AEC Category: Q200; AEC Grade: 0
R10 R23 = CMP-0022003-4: RES, 10.0, 1%, 0.1 W, AEC-Q200 Grade 0, 0603; Manufacturer: Vishay-Dale; Power_W: 100mW; TempCo: 100 ppm/C; Value_Code: 10R0; Value: 10.0; EIA_Code: E96; Res_ohm: 10; SizeX_mm: 1.6; SizeY_mm: 0.8; SizeZ_mm: 1; Value2: 0.1W; SizeArea_mm2: 1.28; AEC Qualified: Y; VDC_V: 75V; AEC Category: Q200; AEC Grade: 0
R11 R24 = CMP-0021048-3: RES, 150k, 1%, 0.125 W, AEC-Q200 Grade 0, 0805; Manufacturer: Vishay-Dale; Power_W: 125mW; TempCo: 100 ppm/C; Value_Code: 215k; Value: 215k; EIA_Code: E96; SizeX_mm: 2; SizeY_mm: 1.25; SizeZ_mm: 1.45; Value2: 0.125W; SizeArea_mm2: 2.5; AEC Qualified: Y; VDC_V: 150V; AEC Category: Q200; AEC Grade: 0
R12 R25 = CMP-0022588-5: RES, 750, 1%, 0.1 W, AEC-Q200 Grade 0, 0603; Manufacturer: Vishay-Dale; Power_W: 100mW; TempCo: 100 ppm/C; Value_Code: 750R; Value: 750; EIA_Code: E96; SizeX_mm: 1.6; SizeY_mm: 0.8; SizeZ_mm: 1; Value2: 0.1W; SizeArea_mm2: 1.28; AEC Qualified: Y; VDC_V: 75V; AEC Category: Q200; AEC Grade: 0
R13 R26 = CMP-0015054-3: RES, 0.01, 1%, 1 W, AEC-Q200 Grade 0, 0612; Manufacturer: Panasonic; AEC Qualified: Y; Value: 0.01; Value2: 1W; SizeX_mm: 1.6; Value_Code: R010; SizeY_mm: 3.2; AEC Grade: 0; U/M: EA; SizeZ_mm: 0.85; SizeAreaWB_mm2: 10.92; Res_ohm: 10m; TempCo: 300 ppm/C; AEC Category: Q200; SizeArea_mm2: 5.12; EIA_Code: E96
R14 R21 = CMP-0022322-4: RES, 309 k, 1%, 0.1 W, AEC-Q200 Grade 0, 0603; Manufacturer: Vishay-Dale; Power_W: 100mW; TempCo: 100 ppm/C; Value: 309k; EIA_Code: E96; SizeX_mm: 1.6; SizeY_mm: 0.8; SizeZ_mm: 1; Value2: 0.1W; SizeArea_mm2: 1.28; AEC Qualified: Y; VDC_V: 75V; AEC Category: Q200; AEC Grade: 0
R15 R27 = CMP-0023475-3: RES, 220 k, 0.1%, 0.1 W, 0603; Manufacturer: Susumu Co Ltd; Power_W: 100mW; TempCo: 25 ppm/C; U/M: EA; Value: 220k; SizeX_mm: 1.6; SizeY_mm: 0.8; SizeZ_mm: 1; Value2: 0.1W; SizeArea_mm2: 1.28; VDC_V: 75V; AEC Category: Q200
R16 = CMP-0025766-4: RES, 27 k, 5%, 0.1 W, AEC-Q200 Grade 0, 0603; Manufacturer: Vishay-Dale; Power_W: 100mW; TempCo: 200 ppm/C; Value_Code: 27k0; Value: 27k; EIA_Code: E24; SizeX_mm: 1.6; SizeY_mm: 0.8; SizeZ_mm: 1; Value2: 0.1W; SizeArea_mm2: 1.28; AEC Qualified: Y; VDC_V: 75V; AEC Category: Q200; AEC Grade: 0
R17 R29 = CMP-0023766-3: RES, 150 k, 0.1%, 0.1 W, 0603; Manufacturer: Yageo America; Power_W: 100mW; TempCo: 25 ppm/C; U/M: EA; Value: 150k; EIA_Code: E192; SizeX_mm: 1.6; SizeY_mm: 0.8; SizeZ_mm: 1; Value2: 0.1W; SizeArea_mm2: 1.28; VDC_V: 75V; AEC Category: Q200
R18 = CMP-0025733-4: RES, 1.5 k, 5%, 0.1 W, AEC-Q200 Grade 0, 0603; Manufacturer: Vishay-Dale; Power_W: 100mW; TempCo: 200 ppm/C; Value_Code: 1k50; Value: 1.5k; EIA_Code: E24; SizeX_mm: 1.6; SizeY_mm: 0.8; SizeZ_mm: 1; Value2: 0.1W; SizeArea_mm2: 1.28; AEC Qualified: Y; VDC_V: 75V; AEC Category: Q200; AEC Grade: 0
R19 = CMP-0025707-4: RES, 11 k, 5%, 0.1 W, AEC-Q200 Grade 0, 0603; Manufacturer: Vishay-Dale; Power_W: 100mW; TempCo: 200 ppm/C; Value_Code: 11k0; Value: 11k; EIA_Code: E24; SizeX_mm: 1.6; SizeY_mm: 0.8; SizeZ_mm: 1; Value2: 0.1W; SizeArea_mm2: 1.28; AEC Qualified: Y; VDC_V: 75V; AEC Category: Q200; AEC Grade: 0
R20 R32 = CMP-0023619-3: RES, 9.10 k, 0.1%, 0.1 W, 0603; Manufacturer: Susumu Co Ltd; Power_W: 100mW; TempCo: 25 ppm/C; Value_Code: 9k10; U/M: EA; Value: 9.10k; Res_ohm: 9.1k; SizeX_mm: 1.6; SizeY_mm: 0.8; SizeZ_mm: 1; Value2: 0.1W; SizeArea_mm2: 1.28; VDC_V: 75V; AEC Category: Q200
R28 = CMP-0022408-4: RES, 402 k, 1%, 0.1 W, AEC-Q200 Grade 0, 0603; Manufacturer: Vishay-Dale; Power_W: 100mW; TempCo: 100 ppm/C; Value: 402k; EIA_Code: E96; SizeX_mm: 1.6; SizeY_mm: 0.8; SizeZ_mm: 1; Value2: 0.1W; SizeArea_mm2: 1.28; AEC Qualified: Y; VDC_V: 75V; AEC Category: Q200; AEC Grade: 0
R30 = CMP-0025786-4: RES, 33 k, 5%, 0.1 W, AEC-Q200 Grade 0, 0603; Manufacturer: Vishay-Dale; Power_W: 100mW; TempCo: 200 ppm/C; Value_Code: 33k0; Value: 33k; EIA_Code: E24; SizeX_mm: 1.6; SizeY_mm: 0.8; SizeZ_mm: 1; Value2: 0.1W; SizeArea_mm2: 1.28; AEC Qualified: Y; VDC_V: 75V; AEC Category: Q200; AEC Grade: 0
R31 = CMP-0022895-5: RES, 1.00 k, 1%, 0.1 W, 0603; Manufacturer: Yageo; Power_W: 100mW; TempCo: 100 ppm/C; Value_Code: 1k00; Value: 1.00k; EIA_Code: E96; Res_ohm: 1k; SizeX_mm: 1.6; SizeY_mm: 0.8; SizeZ_mm: 1; Value2: 0.1W; SizeArea_mm2: 1.28; AEC Qualified: N; VDC_V: 75V; AEC Category: Q200; SizeAreaWB_mm2: 4.68
R33 = CMP-0022066-4: RES, 15.0 k, 1%, 0.1 W, AEC-Q200 Grade 0, 0603; Manufacturer: Vishay-Dale; Power_W: 100mW; TempCo: 100 ppm/C; Value_Code: 15k0; Value: 15.0k; EIA_Code: E96; Res_ohm: 15k; SizeX_mm: 1.6; SizeY_mm: 0.8; SizeZ_mm: 1; Value2: 0.1W; SizeArea_mm2: 1.28; AEC Qualified: Y; VDC_V: 75V; AEC Category: Q200; AEC Grade: 0
U1 U2 = CMP-0091224-1: 10-Bit and 8-Bit, Voltage-Output Digital-to-Analog Converters With Nonvolatile Memory and PMBus™ Compatible I 2C Interface in Tiny 2 × 2 WSON; Manufacturer: Texas Instruments; Number Of Converters: 1; TJmax_C: +150°C; Min Supply Voltage: 1.71V; Interface: I2C; TaMin_C: -40°C; AEC Qualified: No; SizeZ_mm: 0.8mm; Resolution: 10bits; TaMax_C: +125°C; Max Supply Voltage: 5.5V; Standoff Height: 0mm; Sampling Rate: 25ksps; Nominal Supply Current: 0.5mA
U3 U4 = CMP-0085413-1: 2.2-MHz Wide Input Nonsynchronous Boost, Sepic, Flyback Controller, DSS0012B (WSON-12); Alternate Manufacturer: Texas Instruments; Alternate PartNumber: LM5155DSST; SizeAreaWB_mm2: 12; SizeX_mm: 2; SizeZ_mm: 0.8; CompType: IC; SizeArea_mm2: 6; AEC Category: Q200; AEC Qualified: N; SizeY_mm: 3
